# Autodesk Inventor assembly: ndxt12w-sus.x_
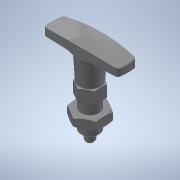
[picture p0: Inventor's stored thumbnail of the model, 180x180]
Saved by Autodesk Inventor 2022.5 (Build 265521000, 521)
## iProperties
Part Number: ndxt12w-sus.x_
Material: 一般
Document SubType Name: Assembly
Designer: ImaoCorp
Sending System: SOLIDWORKS 2017-2017317
MC: AMD64
MC_MODEL: Intel64 Family 6 Model 60 Stepping 3, GenuineIntel
OS: Windows_NT
FRU: Parasolid Version 29.0, build 201,  4-17-2017
FORMAT: text
GUISE: transmit
KEY: ndxt12w-sus
FILE: ndxt12w-sus.x_t
DATE: Wed Sep 04 15:25:16 2019
Author: ImaoCorp
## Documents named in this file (3)
- X:\14_SW2022-Inv2022\00_全2023-1023新製品(TCC)まで\n\ndxt12w-sus\NDXT12W-SUS.iam
- X:\14_SW2022-Inv2022\00_全2023-1023新製品(TCC)まで\n\ndxt12w-sus\ndxt12w-sus_01.ipt
- X:\14_SW2022-Inv2022\00_全2023-1023新製品(TCC)まで\n\ndxt12w-sus\ndxt12w-sus_02.ipt
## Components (2 placed, 2 different names)
1. ndxt12w-sus_01
2. ndxt12w-sus_02
